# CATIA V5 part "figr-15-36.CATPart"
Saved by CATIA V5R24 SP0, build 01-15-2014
Part number: Part1
Bounding box of the stored display mesh (mm): x -63.331 to 107.433, y -39.139 to 39.139, z 0 to 70.926
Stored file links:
  D:\KAVITA\CATIA V5-6R2014 Project_ Kavita\CATIA V5-6R2014_partfiles\Partfiles\c15_catia_v5-6r2014_prt\figr-15-36.CATPart
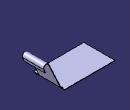
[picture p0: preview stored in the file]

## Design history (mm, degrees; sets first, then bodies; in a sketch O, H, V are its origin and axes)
SheetMetalParameters1: Thickness 1, BendRadius 2, KFactor 0.400515 {= log(min(100,max(20*SheetMetalParameters1.BendRadius,SheetMetalParameters1.Thickness)/SheetMetalParameters1.Thickness))/log(100)/2}, ReliefRadialLength 1, ReliefAxialLength 2, MinimumBendRadius 0
Body1 (main body)
  Sketch1 on xy-plane, origin (0, 0, 0), H (1, 0, 0), V (0, 1, 0)
    line L1 (-63.3311, 39.1393) -> (63.3311, 39.1393)
    line L2 (63.3311, 39.1393) -> (63.3311, -39.1393)
    line L3 (63.3311, -39.1393) -> (-63.3311, -39.1393)
    line L4 (-63.3311, -39.1393) -> (-63.3311, 39.1393)
    horizontal: L1 H, L3 H
    vertical: L2 V, L4 V
    symmetry: L4 L2 V, L1 L3 H
  Wall1: Thickness 1, Profile Sketch1
  d_NewWallOnEdge1: NewWallOnEdge_Edge edge [face of Wall1 | face of Wall1], NewWallOnEdge_Length 67, NewWallOnEdge_HeightLimitOffset 0, NewWallOnEdge_WidthOffset1 -16, NewWallOnEdge_WidthOffset2 -9, NewWallOnEdge_Angle 115, NewWallOnEdge_BendRadiusValue 2 {= SheetMetalParameters1.BendRadius}, NewWallOnEdge_BendTable SheetMetalParameters1, KFacteur 0.400515 {= log(min(100,max(20*d_NewWallOnEdge1.Radius,SheetMetalParameters1.Thickness)/SheetMetalParameters1.Thickness))/log(100)/2}
  Flange1: Angle 4, Length 10, Radius 6, KFacteur 0.5 {= log(min(100,max(20*Flange1.Radius,SheetMetalParameters1.Thickness)/SheetMetalParameters1.Thickness))/log(100)/2}, Guide edge [face of d_NewWallOnEdge1 | face of d_NewWallOnEdge1]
